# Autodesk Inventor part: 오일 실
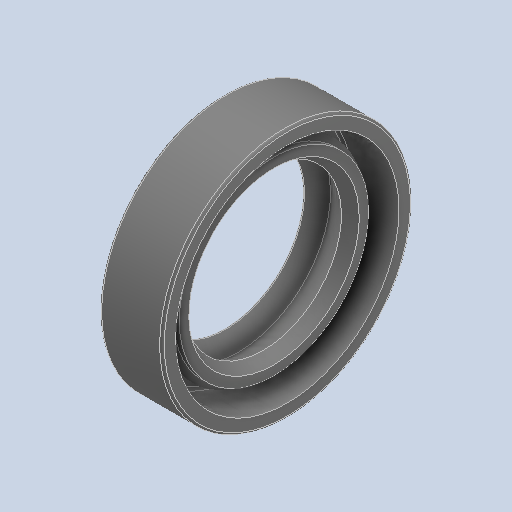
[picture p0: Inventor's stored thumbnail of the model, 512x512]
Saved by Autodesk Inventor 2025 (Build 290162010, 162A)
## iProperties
Created: 2024-08
Part Number: 오일 실
Material: 고무
Description: 오일-실
Document SubType Name: Modeling
Designer: 학생
Density: 0.93 g/cm^3
Appearance: 기본값
Author: jhkim
Sending System: Autodesk Inventor 2025
Preprocessor: ST-DEVELOPER v20
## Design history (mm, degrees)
feature "Solid1"
node "솔리드1"
